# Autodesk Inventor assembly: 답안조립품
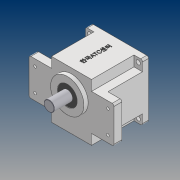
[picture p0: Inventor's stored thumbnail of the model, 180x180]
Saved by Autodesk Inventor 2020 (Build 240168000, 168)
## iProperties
Created: 2020-07
Part Number: 답안조립품
Document SubType Name: Assembly
Designer: PC312-
Author: PC312-
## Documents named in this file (10)
- C:\Users\PC312-\Desktop\700718V1010\답안조립품.iam
- C:\Users\PC312-\Desktop\700718V1010\본체.ipt
- C:\Users\PC312-\Desktop\700718V1010\메인 축.ipt
- C:\Users\PC312-\Desktop\700718V1010\커버.ipt
- C:\Users\PC312-\Desktop\700718V1010\베어링 608.ipt
- C:\Users\PC312-\Desktop\700718V1010\베어링 6003.ipt
- C:\Users\PC312-\Desktop\700718V1010\서브 축.ipt
- C:\Users\PC312-\Desktop\700718V1010\오일 실 17 32 8.ipt
- C:\Users\PC312-\Desktop\700718V1010\오일 실 8 22 7.ipt
- C:\Users\PC312-\Desktop\700718V1010\볼트 M4.ipt
